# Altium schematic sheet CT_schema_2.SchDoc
size 276 x 169 mm
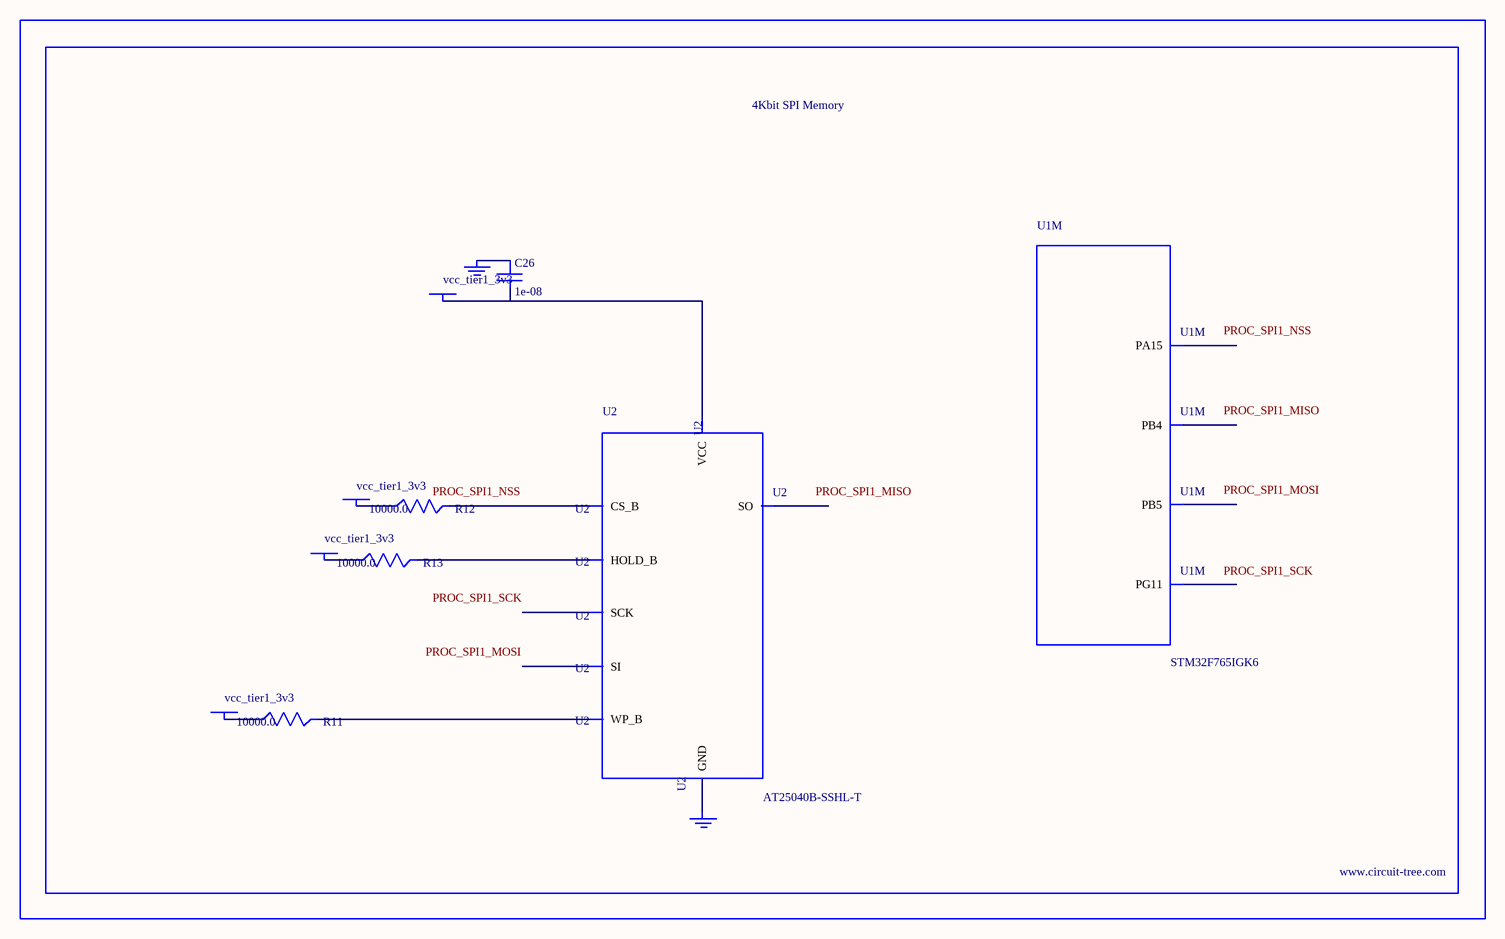
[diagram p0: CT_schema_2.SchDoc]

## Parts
BORDER1  (no value)
C26  1e-08  [C0402]
GND_INSTANCE_1_0  (no value)
GND_INSTANCE_1_1  (no value)
POWER_INSTANCE_1_0  vcc_tier1_3v3
POWER_INSTANCE_1_1  vcc_tier1_3v3
POWER_INSTANCE_1_2  vcc_tier1_3v3
POWER_INSTANCE_1_3  vcc_tier1_3v3
R11  10000.0  [R0603]
R12  10000.0  [R0603]
R13  10000.0  [R0603]
U1  STM32F765IGK6  [UFBGA176_25]  (part M of 17)
U2  AT25040B-SSHL-T  [SOIC-8]

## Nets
NetC26_1: C26.1 GND_INSTANCE_1_0.0(GND)
NetC26_2: C26.2 POWER_INSTANCE_1_3.0(PWR) U2.8(VCC)
NetGND_INSTANCE_1_1_0: GND_INSTANCE_1_1.0(GND) U2.4(GND)
NetPOWER_INSTANCE_1_0_0: POWER_INSTANCE_1_0.0(PWR) R12.1
NetPOWER_INSTANCE_1_1_0: POWER_INSTANCE_1_1.0(PWR) R11.1
NetPOWER_INSTANCE_1_2_0: POWER_INSTANCE_1_2.0(PWR) R13.1
NetR11_2: R11.2 U2.3(WP_B)
NetR12_2: R12.2 U2.1(CS_B)
NetR13_2: R13.2 U2.7(HOLD_B)

Not connected (* = marked no-connect by the designer): U1 A6(PB5) A9(PB4) A13(PA15) B9(PG11); U2 2(SO) 5(SI) 6(SCK)

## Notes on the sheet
- Labels drawn without touching a wire or pin: PROC_SPI1_MISO, PROC_SPI1_MOSI, PROC_SPI1_NSS, PROC_SPI1_SCK

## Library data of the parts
BORDER1 = BORDER_PAGE1
C26 = C0402C103K3RAC
GND_INSTANCE_1_0 GND_INSTANCE_1_1 = GND
POWER_INSTANCE_1_0-POWER_INSTANCE_1_3 = PWR
R11-R13 = RC0603JR-0710KL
